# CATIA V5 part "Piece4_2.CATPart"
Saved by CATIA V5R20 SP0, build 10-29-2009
Part number: Pièce4
Bounding box of the stored display mesh (mm): x 5 to 10, y -24.191 to 60.518, z -89.815 to 36
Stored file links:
  C:\Users\ASUS\Desktop\Think Motion IAO\Piece4_2.CATPart
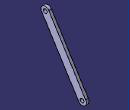
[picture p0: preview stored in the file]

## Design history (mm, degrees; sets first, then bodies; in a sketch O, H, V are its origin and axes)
Body1 (main body)
  Plane1: stored without definition
  Point1 "Point.E": stored without definition
  Point2 "Point.D": stored without definition
  Point3 "Point.E": stored without definition
  Point4 "Point.D": stored without definition
  Sketch1 on Plane1, origin (0, 0, 0), H (0, 1, 0), V (0, 0, 1)
    construction line L1 (52.6852, -81.9821) -> (-16.3583, 28.1678)
    line L2 (46.0459, -86.1437) -> (-22.9977, 24.0061)
    line L3 (-9.719, 32.3294) -> (59.3246, -77.8204)
    arc A1 centre (-16.3583, 28.1678) radius 7.8358 from (-22.9977, 24.0061) to (-9.719, 32.3294) cw
    arc A2 centre (52.6852, -81.9821) radius 7.8358 from (59.3246, -77.8204) to (46.0459, -86.1437) cw
    reference projected point E1 (52.6852, -81.9821) from Point1
    reference projected point E2 (-16.3583, 28.1678) from Point2
    circle A3 centre (52.6852, -81.9821) radius 3.5
    reference projected point E3 (52.6852, -81.9821) from Point3
    circle A4 centre (-16.3583, 28.1678) radius 3.5
    reference projected point E4 (-16.3583, 28.1678) from Point4
    distance L1 L2 = 7.8358
    radius A3 = 3.5
    radius A4 = 3.5
    tangency: A1 L2, A2 L2, A1 L3, A2 L3
    concentricity: A2 E1, A1 E2, A3 E3, A4 E4
  Pad1: profile Sketch1, direction (1, 0, 0), length 10, opposite side length -5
